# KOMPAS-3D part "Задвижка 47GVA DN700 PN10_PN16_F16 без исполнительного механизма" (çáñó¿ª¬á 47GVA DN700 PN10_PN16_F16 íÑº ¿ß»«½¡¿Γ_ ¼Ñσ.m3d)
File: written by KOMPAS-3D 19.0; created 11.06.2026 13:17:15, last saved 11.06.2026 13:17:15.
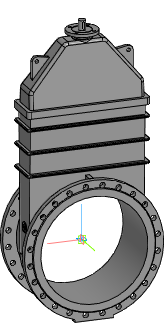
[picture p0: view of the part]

Document properties: Автор: Евгений; Полное имя файла: Z:\3.Личные\kachalov\001_3d для проектировщиков\2.2 Тип 47GVA, 47GVA.Z\_stp\_stp_Задвижка 47GVA DN40-DN1000 без исп.мех\Задвижка 47GVA DN700 PN10_PN16_F16 без исполнит_ мех.m3d

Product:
- Part/product: Задвижка 47GVA DN700 PN10_PN16_F16 без исполнительного механизма

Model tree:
1. Операция без истории:1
